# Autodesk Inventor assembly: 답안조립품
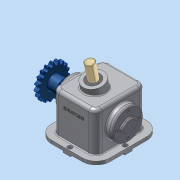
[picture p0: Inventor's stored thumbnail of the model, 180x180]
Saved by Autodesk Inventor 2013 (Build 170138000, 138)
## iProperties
Created: 2014-11
Part Number: 답안조립품
Document SubType Name: Assembly
Designer: WINDOWS7
Author: WINDOWS7
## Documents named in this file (13)
- C:\Users\WINDOWS7\Desktop\441123v1001\답안조립품.iam
- C:\Users\WINDOWS7\Desktop\441123v1001\5-체인 스프로킷.ipt
- C:\Users\WINDOWS7\Desktop\441123v1001\M4x0.5.ipt
- C:\Users\WINDOWS7\Desktop\441123v1001\뒤커버.ipt
- C:\Users\WINDOWS7\Desktop\441123v1001\멈춤나사 M5x0.5.ipt
- C:\Users\WINDOWS7\Desktop\441123v1001\베어링 6205.ipt
- C:\Users\WINDOWS7\Desktop\441123v1001\본체.ipt
- C:\Users\WINDOWS7\Desktop\441123v1001\부시.ipt
- C:\Users\WINDOWS7\Desktop\441123v1001\슬라이드.ipt
- C:\Users\WINDOWS7\Desktop\441123v1001\앞커버.ipt
- C:\Users\WINDOWS7\Desktop\441123v1001\오일실.ipt
- C:\Users\WINDOWS7\Desktop\441123v1001\키 8x8.ipt
- C:\Users\WINDOWS7\Desktop\441123v1001\편심축.ipt
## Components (9 placed, 2 different names)
1. 5-체인 스프로킷:1 — 플러쉬:1
2. M4x0.5:1
3. M4x0.5:3
4. M4x0.5:4
5. M4x0.5:5
6. M4x0.5:2
7. M4x0.5:6
8. M4x0.5:7
9. M4x0.5:8
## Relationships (1: Flush 1)
- 플러쉬:1 [Flush]: 5-체인 스프로킷:1
